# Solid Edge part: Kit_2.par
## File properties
Sűrűség: 0,000 kg/m^3
Pontosság: 0,990
Author: ahadarics
Last saved by: ahadarics
Revision: 76
Username: ahadarics
Dokumentum tartalom típus: 0
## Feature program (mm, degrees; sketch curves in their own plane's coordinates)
base feature "unnamed BaseFeature 1"
sketch for "Furat_1" plane through (0, 8.5, 0) normal (0, 1, 0) x-axis (0, 0, 1)
  hole centre (0, 0) bore radius 2.067
hole "Furat_1" nominal diameter 5 finite  ThreadDepth = 4.5 mm
chamfer "Letörés_1" setback 0.5
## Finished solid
Body 1: solid body, 20 faces, 25 edges, 6 vertices.
  Faces by surface: cylinder 8, plane 7, cone 5
  Edges by curve: circle 18, line 6, intersection 1
Bounding box of the edges (mm): 19.000 x 18.100 x 16.000, from (-9.5, -9.5, -11.5) to (9.5, 8.6, 4.5).
Cylindrical faces by radius (mm): R0.55 x1, R2 x1, R2.06 x1, R2.067 x1, R7.25 x1, R8 x1, R8.6 x1, R9.5 x1
Conical faces (half-angle, radius in mm at the cone's reference point): 30 deg R7.9134 x1, 45 deg R2.567 x1, 45 deg R7.625 x1, 59 deg R1 x1, 59 deg R1.0335 x1
Planar faces by outward normal: +y 2, +z 2, -z 3
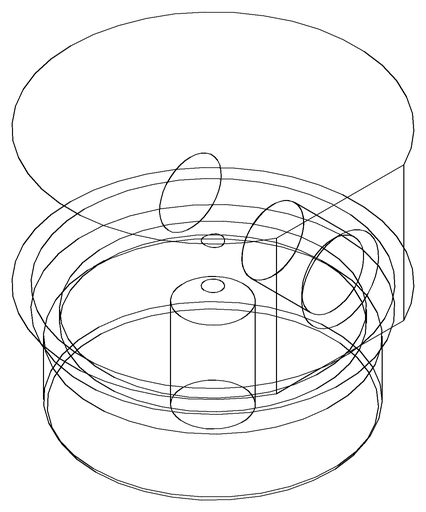
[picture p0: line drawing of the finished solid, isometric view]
